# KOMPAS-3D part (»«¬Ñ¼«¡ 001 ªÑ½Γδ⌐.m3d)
File: created 22.07.2016 16:40:14, last saved 22.07.2016 17:11:04.
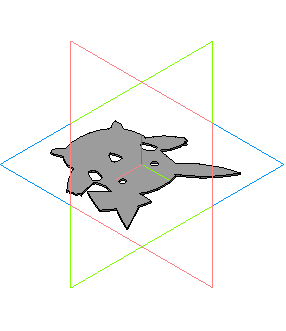
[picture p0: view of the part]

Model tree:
1. Эскиз:1
2. Операция выдавливания:1
     Расстояние 1 = 0.5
